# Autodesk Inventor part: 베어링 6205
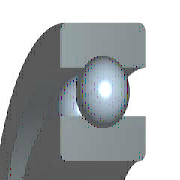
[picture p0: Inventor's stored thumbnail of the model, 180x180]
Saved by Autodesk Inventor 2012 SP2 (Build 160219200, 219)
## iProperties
IsCustomPart: 1
Company: 한국ATC센터
Created: 2014-11
Part Number: 베어링 6205
Material: 강, 연강
Description: 깊은 그루브 볼 베어링
Document SubType Name: Modeling
Standard: KS B 2023
Designer: KYOUNG IL JANG
Standards Organization: KS
Language: ko-KR
Size Designation: 6205 - 25 x 52 x 15
Categories: <MemberInstance><Categories><Category DisplayName="샤프트 부품" InternalName="7f7aeb1f-a693-4053-b835-cee3144e0d98" Mnemonic="SHFT"><Category DisplayName="베어링" Inter
Density: 7.86 g/cm^3
Mass: 129.543 g
Surface Area: 107.326 cm^2
Volume: 16.4813 cm^3
Author: KYOUNG IL JANG
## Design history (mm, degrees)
revolve "본체" stored, may be unused: angle "d6" = 90 deg
revolve "볼" stored, may be unused: angle "d7" = 90 deg
pattern_circular "IDS_ARRAYBALL[SIMPL:T]" dims angle "d3" = 360 deg
body "Solid1"
sketch "스케치" dims "d0" = 7.02 (= -0.26 x WD + 0.26 x BD)
  geometry: L1 (3.99, 19.25)-(11.01, 19.25); L2 (7.5, 19.25)-(7.5, 15.74); L3 (7.5, 19.25)-(7.5, 22.76); L4 (4.892, 16.901)-(0, 16.901); L5 (0, 12.5)-(15, 12.5); L6 (4.892, 21.599)-(0, 21.599); L7 (0, 26)-(15, 26); L8 (15, 12.5)-(15, 16.901); L9 (10.108, 16.901)-(15, 16.901); L10 (10.108, 21.599)-(15, 21.599); L11 (15, 26)-(15, 21.599); L12 (-1.4, 0)-(8.4, 0) reference; L13 (0, -0.3)-(0, 5.3) reference
  constraints: 22 end point, 4 point on line, 2 collinear, 2 perpendicular, 2 symmetric about line, 1 midpoint, 1 parallel, 14 other
  dimensions: "d9" = 25 diameter of L5 L12 (= WD); "d11" = 52 diameter of L7 L12 (= BD); "d12" = 15 distance between parallel lines of L8 L13 (= KB); "d13" = 33.802 diameter of L9 L12 (= 0.326 x BD + 0.674 x WD)
fillet "모깎기1" dims "d1" = 1 (= KRS)
other parameters: "WD" = 25 [user parameter; used in 5 equation terms], "BD" = 52 [user parameter; used in 5 equation terms], "KB" = 15 [user parameter; used in 1 equation term], "KRS" = 1 [user parameter; used in 1 equation term], "d4" = 0, "d5" = 0, "d8" = 0, "d14" = 0, "d15" = 0, "BBA" = 0 [user parameter], "BC0" = 7800000 [user parameter], "BC" = 1.4e+07 [user parameter], "BR" = 26 (= 0.5 x BD) [user parameter], "WR" = 12.5 (= 0.5 x WD) [user parameter]
